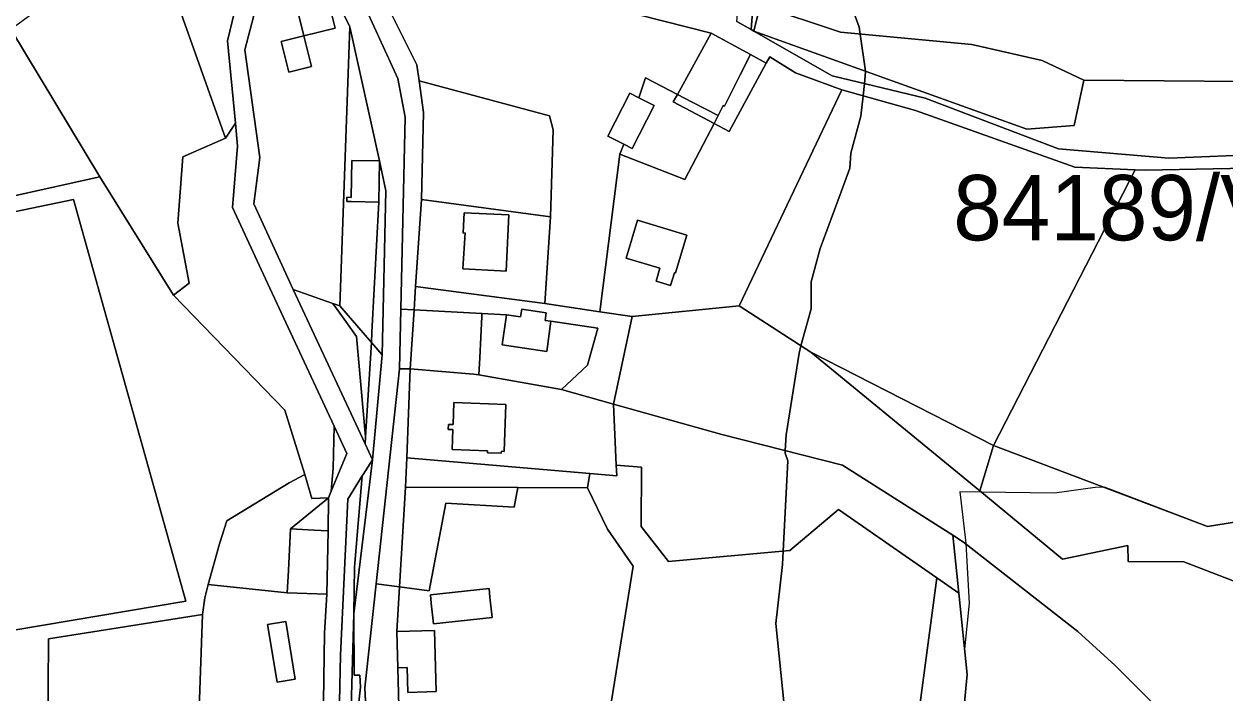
# Model space of a CAD drawing. Extents: x -477304 to -465429, y -1159113 to -1149210.
# Drawn here: x -474180.9 to -473904.9, y -1155678.3 to -1155524.6 of the extents above; entities that cross this region are included whole.
import ezdxf

# ---------------------------------------------------------------- set-up
doc = ezdxf.new("R2010")
doc.units = 0
for name, color, linetype in [('BPEJ_s', 7, 'Continuous'), ('orna_s', 7, 'Continuous'), ('ostatni_s', 7, 'Continuous'), ('PUPFL_s', 7, 'Continuous'), ('trav_porost_s', 7, 'Continuous'), ('voda_s', 7, 'Continuous'), ('zahrada_s', 7, 'Continuous')]:
    doc.layers.add(name, color=color, linetype=linetype)

msp = doc.modelspace()

# ---------------------------------------------------------------- linework, layer by layer
at = {"layer": 'BPEJ_s'}
for points in [[(-473991.09, -1155519.44), (-473988.96, -1155525.39), (-473988.74, -1155526.95), (-473987.49, -1155535.49), (-473987.48, -1155535.6), (-473987.76, -1155538.33), (-473988.05, -1155541.12), (-473988.54, -1155545.81), (-473990.88, -1155554.31), (-473991.09, -1155557.71), (-473993.09, -1155563.15), (-473997.89, -1155576.21), (-474000.02, -1155583.87), (-474000.02, -1155590.03), (-474002.33, -1155598.56), (-474002.78, -1155600.24), (-474005.76, -1155618.95), (-474005.94, -1155622.6), (-474005.97, -1155623.21), (-474005.34, -1155624.91), (-474006.45, -1155645.7), (-474006.61, -1155648.72), (-474008.1, -1155662.33), (-474006.19, -1155681.04)], [(-474006.19, -1155681.04), (-474008.1, -1155662.33), (-474006.61, -1155648.72), (-474006.45, -1155645.7), (-474005.34, -1155624.91), (-474005.97, -1155623.21), (-474005.94, -1155622.6), (-474005.76, -1155618.95), (-474002.78, -1155600.24), (-474002.33, -1155598.56), (-474000.02, -1155590.03), (-474000.02, -1155583.87), (-473997.89, -1155576.21), (-473993.09, -1155563.15), (-473991.09, -1155557.71), (-473990.88, -1155554.31), (-473988.54, -1155545.81), (-473988.05, -1155541.12), (-473987.76, -1155538.33), (-473987.48, -1155535.6), (-473987.49, -1155535.49), (-473988.74, -1155526.95), (-473988.96, -1155525.39), (-473991.09, -1155519.44)], [(-473848.69, -1155630.39), (-473908.89, -1155639.99), (-473932.59, -1155631.03), (-473934.74, -1155631.07), (-473944.1, -1155632.35), (-473960.89, -1155632.13), (-473965.83, -1155632.07), (-473964.51, -1155643.19), (-473964.46, -1155643.97), (-473963.66, -1155657.65), (-473964.71, -1155668.2), (-473964.11, -1155674), (-473967.41, -1155708.54)], [(-473848.69, -1155630.39), (-473908.89, -1155639.99), (-473932.59, -1155631.03), (-473934.74, -1155631.07), (-473944.1, -1155632.35), (-473960.89, -1155632.13), (-473965.83, -1155632.07), (-473964.51, -1155643.19), (-473964.46, -1155643.97), (-473963.66, -1155657.65), (-473964.71, -1155668.2), (-473964.11, -1155674), (-473967.41, -1155708.54)]]:
    msp.add_lwpolyline(points, dxfattribs=at)
at = {"layer": 'orna_s'}
for points in [[(-474120.04, -1155535.69), (-474114.8, -1155534.39), (-474116.55, -1155527.33), (-474109.4, -1155525.56), (-474113.04, -1155510.85), (-474106, -1155525.26), (-474108.34, -1155589.32), (-474109.89, -1155588.78), (-474119.05, -1155585.63), (-474128.1, -1155565.91), (-474126.7, -1155555.26), (-474130.15, -1155530.54), (-474124.88, -1155510.36), (-474130.05, -1155496.06), (-474121.57, -1155497.2), (-474113.04, -1155510.85), (-474120.19, -1155512.62), (-474116.55, -1155527.33), (-474121.79, -1155528.62)], [(-474163.44, -1155559.72), (-474189.42, -1155565.49), (-474191.72, -1155562.64), (-474209.38, -1155540.77), (-474187.72, -1155528.03), (-474183.95, -1155525.81)], [(-473992.92, -1155539.75), (-473976.02, -1155544.52), (-473939.42, -1155557.53), (-473925.51, -1155558.09), (-473958.1, -1155621.4), (-474000.07, -1155600.02), (-474016.5, -1155589.39)], [(-474077.6, -1155605.01), (-474076.36, -1155605.23), (-474057.38, -1155608.58), (-474045.39, -1155611.93), (-474044.78, -1155625.92), (-474044.67, -1155628.43), (-474050.87, -1155627.89), (-474092.93, -1155624.24), (-474092.13, -1155603.85)], [(-474071.19, -1155622.75), (-474070.58, -1155622.77), (-474070.18, -1155612), (-474082.09, -1155611.56), (-474082.28, -1155616.62), (-474083.37, -1155616.58), (-474083.42, -1155617.72), (-474082.32, -1155617.76), (-474082.49, -1155622.37), (-474074.35, -1155622.64), (-474074.37, -1155623.08), (-474071.2, -1155623.19)]]:
    msp.add_lwpolyline(points, close=True, dxfattribs=at)
at = {"layer": 'ostatni_s'}
for points in [[(-474013.28, -1155496.79), (-474012.11, -1155503.75), (-474013.76, -1155525.92), (-474017.08, -1155524.02), (-474015.28, -1155504.31), (-474016.31, -1155498.35), (-474021.23, -1155477.42), (-474018.49, -1155476.25)], [(-474120.19, -1155512.62), (-474113.04, -1155510.85), (-474109.4, -1155525.56), (-474116.55, -1155527.33)], [(-474094.96, -1155537.16), (-474106.76, -1155511.38), (-474102.75, -1155509.76), (-474090.63, -1155533.99), (-474090.11, -1155537.68), (-474089.09, -1155544.94), (-474089.57, -1155564.92), (-474090.9, -1155584.92), (-474091.25, -1155590.25), (-474094.33, -1155590.11), (-474093.31, -1155546.05)], [(-474048.57, -1155590.73), (-474061.21, -1155588.85), (-474059.87, -1155568.94), (-474059.26, -1155548.91), (-474060.13, -1155545.69), (-474090.11, -1155537.68), (-474090.63, -1155533.99), (-474102.75, -1155509.76), (-474077.66, -1155512.77), (-474023, -1155526.75), (-474030.73, -1155540.8), (-474038.07, -1155536.96), (-474039.57, -1155541.56), (-474041.66, -1155540.48), (-474046.69, -1155550.41), (-474043.06, -1155552.24), (-474043.94, -1155554.5)], [(-474121.79, -1155528.62), (-474116.55, -1155527.33), (-474114.8, -1155534.39), (-474120.04, -1155535.69)], [(-474019.93, -1155543.5), (-474020.19, -1155543.37), (-474021.39, -1155545.68), (-474027.33, -1155542.58), (-474030.73, -1155540.8), (-474023, -1155526.75), (-474013.95, -1155531.67), (-474016.29, -1155536.3)], [(-474059.26, -1155548.91), (-474059.87, -1155568.94), (-474089.57, -1155564.92), (-474089.09, -1155544.94), (-474090.11, -1155537.68), (-474060.13, -1155545.69)], [(-474043.94, -1155554.5), (-474043.06, -1155552.24), (-474041.12, -1155553.22), (-474036.1, -1155543.34), (-474039.57, -1155541.56), (-474038.07, -1155536.96), (-474030.73, -1155540.8), (-474031.69, -1155542.54), (-474022.31, -1155547.45), (-474029.01, -1155560.34)], [(-474036.1, -1155543.34), (-474041.12, -1155553.22), (-474043.06, -1155552.24), (-474046.69, -1155550.41), (-474041.66, -1155540.48), (-474039.57, -1155541.56)], [(-474027.33, -1155542.58), (-474021.39, -1155545.68), (-474022.31, -1155547.45), (-474031.69, -1155542.54), (-474030.73, -1155540.8)], [(-474106.69, -1155564.42), (-474105.7, -1155564.44), (-474105.55, -1155555.97), (-474099.18, -1155556.08), (-474099.34, -1155565.54), (-474105.71, -1155565.43), (-474106.71, -1155565.42)], [(-474097.75, -1155562.95), (-474098.61, -1155600.59), (-474101.07, -1155597.74), (-474100.93, -1155595.43), (-474099.34, -1155565.54), (-474099.18, -1155556.08)], [(-474061.21, -1155588.85), (-474090.9, -1155584.92), (-474089.57, -1155564.92), (-474059.87, -1155568.94)], [(-474080.03, -1155580.82), (-474079.52, -1155572.58), (-474079.98, -1155572.64), (-474079.88, -1155571.01), (-474079.72, -1155567.99), (-474069.48, -1155568.48), (-474070.12, -1155581.36), (-474071.36, -1155581.29)], [(-474080.03, -1155580.82), (-474071.36, -1155581.29), (-474070.12, -1155581.36), (-474069.48, -1155568.48), (-474079.72, -1155567.99), (-474079.88, -1155571.01), (-474079.98, -1155572.64), (-474079.52, -1155572.58)], [(-474039.89, -1155569.69), (-474028.58, -1155573.09), (-474031.2, -1155581.81), (-474031.39, -1155581.75), (-474032.29, -1155584.71), (-474035.62, -1155583.67), (-474034.73, -1155580.74), (-474042.51, -1155578.38)], [(-474102.42, -1155619.45), (-474104.45, -1155596.37), (-474108.44, -1155590.78), (-474109.89, -1155588.78), (-474108.34, -1155589.32), (-474101.07, -1155597.74)], [(-474094.6, -1155603.82), (-474094.33, -1155590.11), (-474091.25, -1155590.25), (-474092.13, -1155603.85)], [(-474077.6, -1155605.01), (-474092.13, -1155603.85), (-474091.25, -1155590.25), (-474075.64, -1155591.1), (-474075.67, -1155591.78), (-474076.16, -1155601.33), (-474076.36, -1155605.23)], [(-474059.79, -1155592.9), (-474049.05, -1155594.48), (-474051.38, -1155602.96), (-474057.38, -1155608.58), (-474076.36, -1155605.23), (-474076.16, -1155601.33), (-474075.67, -1155591.78), (-474075.64, -1155591.1), (-474069.99, -1155591.41), (-474071, -1155598.31), (-474060.75, -1155599.81)], [(-474069.99, -1155591.41), (-474066.77, -1155591.88), (-474066.51, -1155590.11), (-474060.89, -1155590.93), (-474061.15, -1155592.7), (-474059.79, -1155592.9), (-474060.75, -1155599.81), (-474071, -1155598.31)], [(-474102.42, -1155619.45), (-474101.07, -1155597.74), (-474098.61, -1155600.59), (-474100.82, -1155624.69), (-474102.52, -1155621.05)], [(-474000.07, -1155600.02), (-473958.1, -1155621.4), (-473961.26, -1155631.83)], [(-474099.93, -1155653.17), (-474094.6, -1155603.82), (-474092.13, -1155603.85), (-474092.93, -1155624.24), (-474093.22, -1155630.98), (-474094.6, -1155653.87)], [(-474083.42, -1155617.72), (-474083.37, -1155616.58), (-474082.28, -1155616.62), (-474082.09, -1155611.56), (-474070.18, -1155612), (-474070.58, -1155622.77), (-474071.19, -1155622.75), (-474071.2, -1155623.19), (-474074.37, -1155623.08), (-474074.35, -1155622.64), (-474082.49, -1155622.37), (-474082.32, -1155617.76)], [(-474032.8, -1155648.08), (-474039.04, -1155640.04), (-474038.98, -1155626.41), (-474044.78, -1155625.92), (-474045.39, -1155611.93), (-474020.51, -1155618.9), (-473992.75, -1155625.96), (-473967.43, -1155642.02), (-473966.05, -1155655.32), (-473971.07, -1155651.85), (-473993.73, -1155636.15), (-474004.92, -1155645.56)], [(-474103.15, -1155628.39), (-474102.96, -1155628.09), (-474100.82, -1155624.69), (-474105.06, -1155660.05), (-474104.93, -1155649.33)], [(-474119.62, -1155640.59), (-474120.14, -1155650.15), (-474120.43, -1155655.28), (-474138.54, -1155653.38), (-474135.99, -1155643.99), (-474134.27, -1155638.7), (-474119.93, -1155630.01), (-474116.35, -1155628.08), (-474114.71, -1155633.58), (-474110.92, -1155633.47)], [(-474119.62, -1155640.59), (-474114.19, -1155640.88), (-474111, -1155641.05), (-474111.28, -1155655.55), (-474120.43, -1155655.28), (-474120.14, -1155650.15)], [(-474134.03, -1155721.98), (-474136.48, -1155720.97), (-474135.84, -1155705.71), (-474140.61, -1155681.9), (-474139.86, -1155660.23), (-474139.36, -1155656.41), (-474138.54, -1155653.38), (-474120.43, -1155655.28), (-474111.28, -1155655.55), (-474111.81, -1155664.55), (-474112.3, -1155695.98), (-474116.96, -1155706.52), (-474122.65, -1155715.66), (-474125.58, -1155725.41)], [(-474093.16, -1155706.53), (-474092.82, -1155709.2), (-474090.92, -1155724.05), (-474090.71, -1155725.72), (-474095.24, -1155725.48), (-474101.93, -1155689), (-474102.55, -1155677.11), (-474099.93, -1155653.17), (-474094.6, -1155653.87), (-474095.22, -1155664.14), (-474094.98, -1155672.46), (-474094.7, -1155684.3), (-474093.55, -1155701.01)], [(-474087.31, -1155657.66), (-474087.5, -1155655.75), (-474074.02, -1155654.3), (-474073.84, -1155656.22), (-474073.31, -1155660.96), (-474086.78, -1155662.41)], [(-474120.75, -1155661.88), (-474118.54, -1155675.06), (-474122.69, -1155675.76), (-474124.9, -1155662.57)], [(-474122.69, -1155675.76), (-474118.54, -1155675.06), (-474120.75, -1155661.88), (-474124.9, -1155662.57)], [(-474086.18, -1155677.93), (-474092.71, -1155678.12), (-474092.87, -1155672.4), (-474094.98, -1155672.46), (-474095.22, -1155664.14), (-474086.59, -1155663.88)]]:
    msp.add_lwpolyline(points, close=True, dxfattribs=at)
for points in [[(-474104.58, -1155685.77), (-474103.53, -1155676.96), (-474103.69, -1155674.15), (-474105.01, -1155674.17), (-474105.06, -1155660.05), (-474100.82, -1155624.69), (-474098.61, -1155600.59), (-474097.75, -1155562.95), (-474099.18, -1155556.08), (-474106, -1155525.26), (-474113.04, -1155510.85)], [(-474106.76, -1155511.38), (-474094.96, -1155537.16), (-474093.31, -1155546.05), (-474094.33, -1155590.11), (-474094.6, -1155603.82), (-474099.93, -1155653.17), (-474102.55, -1155677.11), (-474101.93, -1155689)], [(-473892.02, -1155557.57), (-473923.16, -1155558.18), (-473925.51, -1155558.09), (-473939.42, -1155557.53), (-473976.02, -1155544.52), (-473992.92, -1155539.75), (-474003.59, -1155535.82), (-474009.51, -1155532.19), (-474010.3, -1155533.65), (-474013.95, -1155531.67), (-474023, -1155526.75), (-474077.66, -1155512.77)], [(-474017.08, -1155524.02), (-474013.76, -1155525.92), (-474013.16, -1155526.26), (-473995.16, -1155536.54), (-473973.8, -1155541.7), (-473943.17, -1155553.33), (-473917.77, -1155555.45), (-473891.47, -1155554.36)]]:
    msp.add_lwpolyline(points, dxfattribs=at)
at = {"layer": 'PUPFL_s'}
msp.add_lwpolyline([(-473910.84, -1155691.31), (-473930.1, -1155671.93), (-473938.68, -1155664.11), (-473964.95, -1155643.59), (-473967.43, -1155642.02), (-473992.75, -1155625.96), (-474020.51, -1155618.9), (-474045.39, -1155611.93), (-474041.14, -1155591.83), (-474016.5, -1155589.39), (-474000.07, -1155600.02), (-473961.26, -1155631.83), (-473942.23, -1155647.55), (-473927.22, -1155644.37), (-473927.14, -1155648.1), (-473914.33, -1155648.11), (-473902.99, -1155652.53)], dxfattribs=at)
for points in [[(-473859.6, -1155647.97), (-473864.83, -1155643.09), (-473902.99, -1155652.53), (-473914.33, -1155648.11), (-473927.14, -1155648.1), (-473927.22, -1155644.37), (-473942.23, -1155647.55), (-473961.26, -1155631.83), (-473958.1, -1155621.4), (-473908.89, -1155639.99), (-473848.69, -1155630.39), (-473811.57, -1155613.46), (-473804.92, -1155620.25)], [(-473966.05, -1155655.32), (-473967.43, -1155642.02), (-473964.95, -1155643.59), (-473938.68, -1155664.11), (-473930.1, -1155671.93), (-473910.84, -1155691.31), (-473883.01, -1155713.5), (-473850.05, -1155736.72), (-473853.33, -1155767.58), (-473862.3, -1155793.17), (-473887.7, -1155796.3), (-473904.62, -1155794.3), (-473909.29, -1155793.74), (-473930.17, -1155791.28), (-473928.33, -1155763.78), (-473927.65, -1155766.14), (-473924.53, -1155788.25), (-473918.45, -1155786.19), (-473908.23, -1155784.85), (-473906.83, -1155754.08), (-473919.53, -1155708.81), (-473956.06, -1155724.86), (-473968.9, -1155724.17), (-473964.11, -1155674)]]:
    msp.add_lwpolyline(points, close=True, dxfattribs=at)
at = {"layer": 'trav_porost_s'}
for points in [[(-473946.91, -1155532.98), (-473963.06, -1155529.31), (-473993.21, -1155526.54), (-474011.71, -1155520.36), (-474013.16, -1155526.26), (-474013.76, -1155525.92), (-474012.11, -1155503.75), (-474013.28, -1155496.79), (-474009.3, -1155494.9), (-473999.42, -1155490.22), (-473963.55, -1155491.81), (-473941.51, -1155496.62), (-473934.38, -1155500.44), (-473896.04, -1155507.94), (-473871.89, -1155513), (-473863.44, -1155538.16), (-473937.3, -1155537.51)], [(-474130.93, -1155515.12), (-474134.13, -1155528.5), (-474132.32, -1155547.4), (-474134.59, -1155550.86), (-474151.19, -1155504.07), (-474136.98, -1155495.49), (-474132.05, -1155507.62)], [(-474144.43, -1155555.14), (-474145.58, -1155570.4), (-474142.92, -1155584.13), (-474146.56, -1155586.94), (-474163.44, -1155559.72), (-474183.95, -1155525.81), (-474168.59, -1155514.57), (-474164.95, -1155512.37), (-474151.19, -1155504.07), (-474134.59, -1155550.86)], [(-473993.21, -1155526.54), (-473963.06, -1155529.31), (-473946.91, -1155532.98), (-473937.3, -1155537.51), (-473939.57, -1155547.93), (-473950.42, -1155548.77), (-474013.16, -1155526.26), (-474011.71, -1155520.36)], [(-473995.16, -1155536.54), (-474013.16, -1155526.26), (-473950.42, -1155548.77), (-473939.57, -1155547.93), (-473937.3, -1155537.51), (-473863.44, -1155538.16), (-473860.11, -1155547.74), (-473876.88, -1155552.97), (-473891.47, -1155554.36), (-473917.77, -1155555.45), (-473943.17, -1155553.33), (-473973.8, -1155541.7)], [(-473813.02, -1155540.58), (-473806.22, -1155558.68), (-473814.12, -1155576.34), (-473813.55, -1155604.41), (-473816.91, -1155608), (-473811.57, -1155613.46), (-473848.69, -1155630.39), (-473908.89, -1155639.99), (-473958.1, -1155621.4), (-473925.51, -1155558.09), (-473923.16, -1155558.18), (-473892.02, -1155557.57), (-473878.45, -1155556.12), (-473821.71, -1155539.31)], [(-474110.92, -1155633.47), (-474114.71, -1155633.58), (-474116.35, -1155628.08), (-474120.97, -1155613.29), (-474146.56, -1155586.94), (-474142.92, -1155584.13), (-474145.58, -1155570.4), (-474144.43, -1155555.14), (-474134.59, -1155550.86), (-474132.32, -1155547.4), (-474131.82, -1155552.69), (-474132.97, -1155566.76), (-474124.9, -1155584.15), (-474109.64, -1155617.02), (-474109.86, -1155626.62), (-474110.28, -1155631.9)], [(-474183.24, -1155663.83), (-474210.18, -1155661.94), (-474246.51, -1155666.52), (-474274.69, -1155666.51), (-474275.06, -1155660.44), (-474286.64, -1155665.84), (-474324.61, -1155664.18), (-474328.68, -1155629.87), (-474322.44, -1155621.35), (-474318.86, -1155627.25), (-474303.11, -1155621.59), (-474307.35, -1155612.46), (-474298.68, -1155604.62), (-474209.72, -1155573.3), (-474169.54, -1155564.95), (-474143.71, -1155657.14)], [(-474067.44, -1155631.1), (-474093.22, -1155630.98), (-474092.93, -1155624.24), (-474050.87, -1155627.89), (-474051.38, -1155631.18)], [(-474006.49, -1155706.54), (-474008.03, -1155683.03), (-474021.47, -1155683.57), (-474026.74, -1155690.56), (-474047.36, -1155689.09), (-474040.9, -1155649.14), (-474046.83, -1155640.64), (-474051.38, -1155631.18), (-474050.87, -1155627.89), (-474044.67, -1155628.43), (-474044.78, -1155625.92), (-474038.98, -1155626.41), (-474039.04, -1155640.04), (-474032.8, -1155648.08), (-474004.92, -1155645.56), (-473993.73, -1155636.15), (-473971.07, -1155651.85), (-473982.92, -1155740.2), (-473972.05, -1155739.78), (-473963.01, -1155746.28), (-473987.61, -1155742.19), (-473992.14, -1155707.45)], [(-474110.92, -1155633.47), (-474111, -1155641.05), (-474114.19, -1155640.88), (-474119.62, -1155640.59)], [(-474086.59, -1155663.88), (-474095.22, -1155664.14), (-474094.6, -1155653.87), (-474087.81, -1155654.83), (-474083.96, -1155634.65), (-474068.27, -1155635.61), (-474067.44, -1155631.1), (-474051.38, -1155631.18), (-474046.83, -1155640.64), (-474040.9, -1155649.14), (-474047.36, -1155689.09), (-474026.74, -1155690.56), (-474021.47, -1155683.57), (-474008.03, -1155683.03), (-474006.49, -1155706.54), (-474062.8, -1155702.96), (-474093.55, -1155701.01), (-474094.7, -1155684.3), (-474094.98, -1155672.46), (-474092.87, -1155672.4), (-474092.71, -1155678.12), (-474086.18, -1155677.93)], [(-474083.96, -1155634.65), (-474087.81, -1155654.83), (-474094.6, -1155653.87), (-474093.22, -1155630.98), (-474067.44, -1155631.1), (-474068.27, -1155635.61)], [(-473908.23, -1155784.85), (-473918.45, -1155786.19), (-473924.53, -1155788.25), (-473927.65, -1155766.14), (-473928.33, -1155763.78), (-473927.56, -1155752.18), (-473963.01, -1155746.28), (-473972.05, -1155739.78), (-473982.92, -1155740.2), (-473971.07, -1155651.85), (-473966.05, -1155655.32), (-473964.11, -1155674), (-473968.9, -1155724.17), (-473956.06, -1155724.86), (-473919.53, -1155708.81), (-473906.83, -1155754.08)], [(-474073.84, -1155656.22), (-474074.02, -1155654.3), (-474087.5, -1155655.75), (-474087.31, -1155657.66), (-474086.78, -1155662.41), (-474073.31, -1155660.96)], [(-474134.03, -1155721.98), (-474134.28, -1155724.46), (-474139.11, -1155732.61), (-474140.96, -1155753.05), (-474159.89, -1155752.39), (-474159.61, -1155739.19), (-474175.82, -1155742.98), (-474175.26, -1155665.79), (-474139.86, -1155660.23), (-474140.61, -1155681.9), (-474135.84, -1155705.71), (-474136.48, -1155720.97)]]:
    msp.add_lwpolyline(points, close=True, dxfattribs=at)
for points in [[(-474189.42, -1155565.49), (-474163.44, -1155559.72), (-474146.56, -1155586.94), (-474120.97, -1155613.29), (-474116.35, -1155628.08), (-474119.93, -1155630.01), (-474134.27, -1155638.7), (-474135.99, -1155643.99), (-474138.54, -1155653.38), (-474139.36, -1155656.41), (-474139.86, -1155660.23), (-474175.26, -1155665.79), (-474175.82, -1155742.98)], [(-474183.24, -1155663.83), (-474143.71, -1155657.14), (-474169.54, -1155564.95), (-474209.72, -1155573.3)]]:
    msp.add_lwpolyline(points, dxfattribs=at)
at = {"layer": 'voda_s'}
for points in [[(-474124.88, -1155510.36), (-474130.15, -1155530.54), (-474126.7, -1155555.26), (-474128.1, -1155565.91), (-474119.05, -1155585.63), (-474102.52, -1155621.05), (-474100.82, -1155624.69), (-474102.96, -1155628.09), (-474103.15, -1155628.39), (-474106.5, -1155633.72), (-474108.15, -1155669.54), (-474108.86, -1155701.6)], [(-474112.3, -1155695.98), (-474111.81, -1155664.55), (-474111.28, -1155655.55), (-474111, -1155641.05), (-474110.92, -1155633.47), (-474110.28, -1155631.9), (-474106.74, -1155623.26), (-474109.64, -1155617.02), (-474124.9, -1155584.15), (-474132.97, -1155566.76), (-474131.82, -1155552.69), (-474132.32, -1155547.4), (-474134.13, -1155528.5), (-474130.93, -1155515.12)]]:
    msp.add_lwpolyline(points, dxfattribs=at)
for points in [[(-474102.42, -1155619.45), (-474102.52, -1155621.05), (-474119.05, -1155585.63), (-474109.89, -1155588.78), (-474108.44, -1155590.78), (-474104.45, -1155596.37)], [(-474110.28, -1155631.9), (-474109.86, -1155626.62), (-474109.64, -1155617.02), (-474106.74, -1155623.26)], [(-474105.06, -1155660.05), (-474105.8, -1155684.31), (-474106.15, -1155695.66), (-474106.44, -1155697.47), (-474112.79, -1155710.02), (-474108.86, -1155701.6), (-474108.15, -1155669.54), (-474106.5, -1155633.72), (-474103.15, -1155628.39), (-474104.93, -1155649.33)], [(-474103.53, -1155676.96), (-474104.58, -1155685.77), (-474106.15, -1155695.66), (-474105.8, -1155684.31), (-474105.06, -1155660.05), (-474105.01, -1155674.17), (-474103.69, -1155674.15)]]:
    msp.add_lwpolyline(points, close=True, dxfattribs=at)
at = {"layer": 'zahrada_s'}
for points in [[(-474099.18, -1155556.08), (-474105.55, -1155555.97), (-474105.7, -1155564.44), (-474106.69, -1155564.42), (-474106.71, -1155565.42), (-474105.71, -1155565.43), (-474099.34, -1155565.54), (-474100.93, -1155595.43), (-474101.07, -1155597.74), (-474108.34, -1155589.32), (-474106, -1155525.26)], [(-474022.31, -1155547.45), (-474018.8, -1155549.29), (-474010.3, -1155533.65), (-474009.51, -1155532.19), (-474003.59, -1155535.82), (-473992.92, -1155539.75), (-474016.5, -1155589.39), (-474041.14, -1155591.83), (-474048.57, -1155590.73), (-474043.94, -1155554.5), (-474029.01, -1155560.34)], [(-474022.31, -1155547.45), (-474021.39, -1155545.68), (-474020.19, -1155543.37), (-474019.93, -1155543.5), (-474016.29, -1155536.3), (-474013.95, -1155531.67), (-474010.3, -1155533.65), (-474018.8, -1155549.29)], [(-474034.73, -1155580.74), (-474035.62, -1155583.67), (-474032.29, -1155584.71), (-474031.39, -1155581.75), (-474031.2, -1155581.81), (-474028.58, -1155573.09), (-474039.89, -1155569.69), (-474042.51, -1155578.38)], [(-474045.39, -1155611.93), (-474057.38, -1155608.58), (-474051.38, -1155602.96), (-474049.05, -1155594.48), (-474059.79, -1155592.9), (-474061.15, -1155592.7), (-474060.89, -1155590.93), (-474066.51, -1155590.11), (-474066.77, -1155591.88), (-474069.99, -1155591.41), (-474075.64, -1155591.1), (-474091.25, -1155590.25), (-474090.9, -1155584.92), (-474061.21, -1155588.85), (-474048.57, -1155590.73), (-474041.14, -1155591.83)]]:
    msp.add_lwpolyline(points, close=True, dxfattribs=at)

# ---------------------------------------------------------------- texts
at = {"layer": 'BPEJ_s'}
msp.add_text('84189/V.', height=15, dxfattribs=at).set_placement((-473967.34, -1155574.31))

doc.saveas('drawing.dxf')
